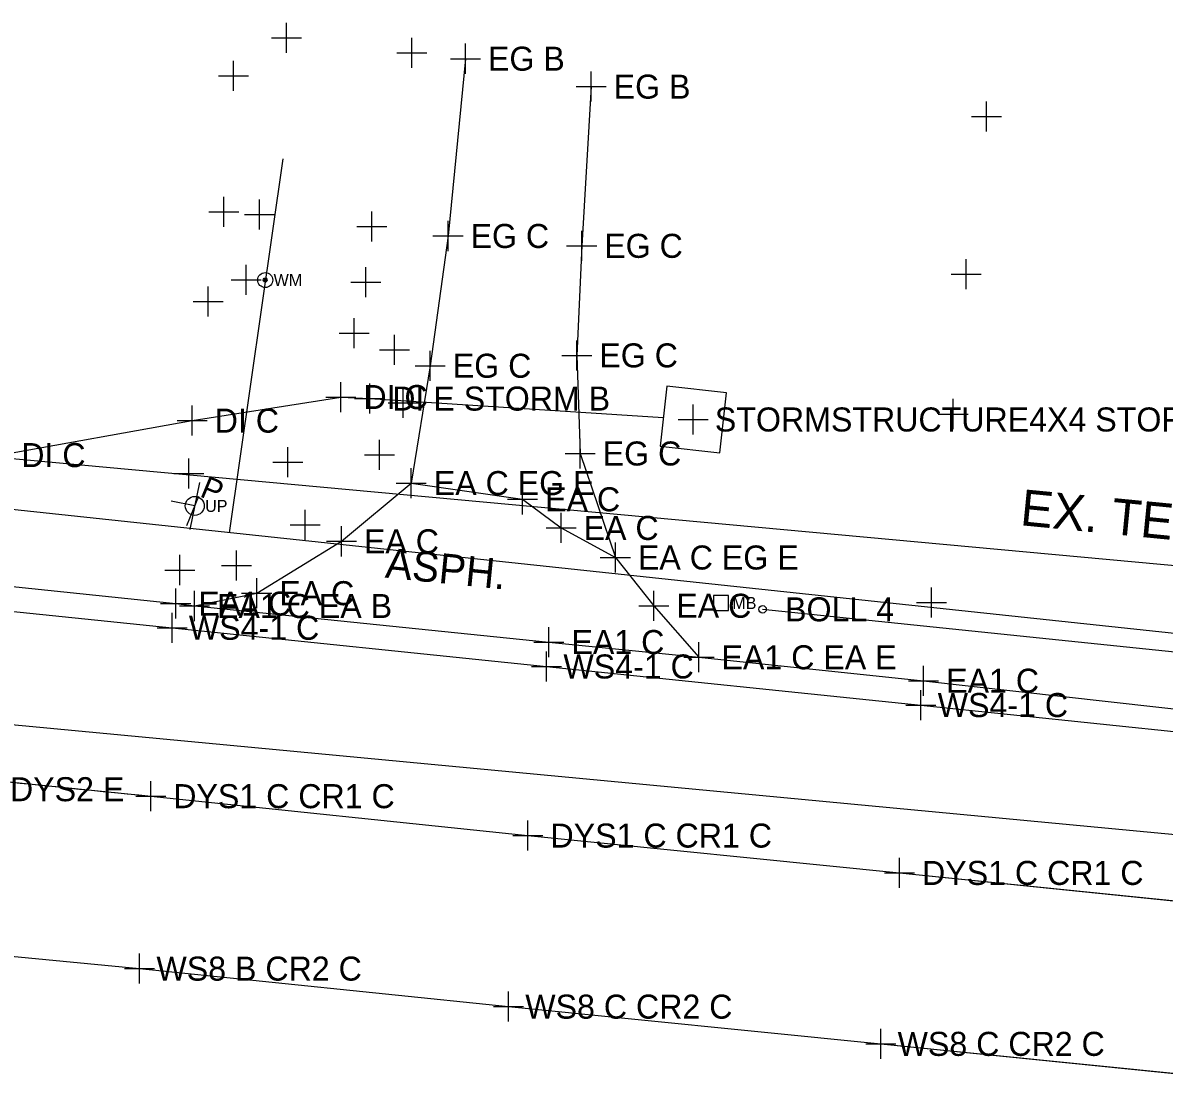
# Model space of a CAD drawing. Extents: x 1363693 to 1365209, y 422201 to 424153.
# Drawn here: x 1363888 to 1363964, y 423133.2 to 423203.8 of the extents above; entities that cross this region are included whole.
import ezdxf

# ---------------------------------------------------------------- set-up
doc = ezdxf.new("R2010")
doc.units = 0
for name, color, linetype in [('DR_X_Cells', 7, 'Continuous'), ('DR_X_Ditch', 7, 'Continuous'), ('DR_X_Storm_Sewer', 7, 'Continuous'), ('O-ALGN-BASELINE-WERK-CL-RW', 7, 'Continuous'), ('OWNERS', 7, 'Continuous'), ('PM_X_Channelizing_Line', 7, 'Continuous'), ('PM_X_CL_Double_Solid', 7, 'Continuous'), ('PM_X_Edge_Line', 7, 'Continuous'), ('PV_X_Driveway', 7, 'Continuous'), ('RD_X_Misc_Items', 7, 'Continuous'), ('RD_X_Text', 7, 'Continuous'), ('SN_X_Public', 7, 'Continuous'), ('SV_X_Original_Ground', 7, 'Continuous'), ('SV_X_Shot_Marker', 7, 'Continuous'), ('UT_X_Misc_Cells', 7, 'Continuous'), ('UT_X_Telecom_FO', 7, 'Continuous'), ('UT_X_Telecom_Text', 7, 'Continuous'), ('UT_X_Unknown_Cells', 7, 'Continuous'), ('UT_X_Water', 7, 'Continuous'), ('UT_X_Water_Text', 7, 'Continuous')]:
    doc.layers.add(name, color=color, linetype=linetype)

msp = doc.modelspace()

# ---------------------------------------------------------------- linework, layer by layer
at = {"layer": 'DR_X_Cells'}
msp.add_lwpolyline([(1363930.439, 423175.618), (1363934.414, 423175.175), (1363934.857, 423179.15), (1363930.882, 423179.593)], close=True, dxfattribs=at)
msp.add_lwpolyline([(1363930.439, 423175.618), (1363934.414, 423175.175), (1363934.857, 423179.15), (1363930.882, 423179.593)], close=True, dxfattribs=at)
at = {"layer": 'DR_X_Ditch'}
for p, q in [((1363899.298, 423177.309), (1363909.19, 423178.878)), ((1363899.298, 423177.309), (1363909.19, 423178.878)), ((1363909.19, 423178.878), (1363911.113, 423178.776)), ((1363909.19, 423178.878), (1363911.113, 423178.776)), ((1363886.422, 423175.014), (1363899.298, 423177.309)), ((1363886.422, 423175.014), (1363899.298, 423177.309))]:
    msp.add_line(p, q, dxfattribs=at)
at = {"layer": 'DR_X_Storm_Sewer'}
msp.add_line((1363911.113, 423178.776), (1363930.65, 423177.513), dxfattribs=at)
msp.add_line((1363911.113, 423178.776), (1363930.65, 423177.513), dxfattribs=at)
at = {"layer": 'O-ALGN-BASELINE-WERK-CL-RW'}
for points in [[(1363796.941, 423162.598), (1363822.036, 423159.943), (1363846.84, 423157.4), (1363871.296, 423154.865), (1363896.538, 423152.307), (1363921.646, 423149.685), (1363946.375, 423147.199), (1363971.317, 423144.667)], [(1363796.066, 423152.4), (1363820.538, 423149.019), (1363870.147, 423143.298), (1363895.8, 423140.828), (1363920.348, 423138.297), (1363945.13, 423135.819), (1363969.932, 423133.318)]]:
    msp.add_lwpolyline(points, dxfattribs=at)
at = {"layer": 'OWNERS'}
for points in [[(1363798.682, 423175.613), (1363823.663, 423174.201), (1363833.723, 423173.351), (1363848.588, 423171.533), (1363855.604, 423170.527), (1363873.275, 423167.734), (1363898.2, 423165.13), (1363899.452, 423164.968), (1363923.042, 423162.567), (1363933.03, 423161.553), (1363947.981, 423159.993), (1363972.757, 423157.214), (1363997.631, 423154.599), (1364022.422, 423152.18), (1364047.381, 423149.744), (1364072.232, 423147.292), (1364097.055, 423144.216), (1364103.808, 423143.454)], [(1363899.452, 423164.968), (1363903.591, 423165.821), (1363909.229, 423169.273), (1363913.878, 423173.149), (1363921.291, 423172.069), (1363923.85, 423170.164), (1363927.464, 423168.196), (1363930.02, 423164.983), (1363933.03, 423161.553)]]:
    msp.add_lwpolyline(points, dxfattribs=at)
at = {"layer": 'PM_X_Channelizing_Line'}
for p, q in [((1363873.089, 423166.093), (1363897.96, 423163.517)), ((1363897.96, 423163.517), (1363922.888, 423160.941)), ((1363922.888, 423160.941), (1363947.8, 423158.373)), ((1363947.8, 423158.373), (1363972.601, 423155.781)), ((1363896.538, 423152.307), (1363921.646, 423149.685)), ((1363921.646, 423149.685), (1363946.375, 423147.199)), ((1363946.375, 423147.199), (1363971.317, 423144.667)), ((1363895.8, 423140.828), (1363920.348, 423138.297)), ((1363895.8, 423140.828), (1363920.348, 423138.297)), ((1363920.348, 423138.297), (1363945.13, 423135.819)), ((1363920.348, 423138.297), (1363945.13, 423135.819)), ((1363945.13, 423135.819), (1363969.932, 423133.318)), ((1363945.13, 423135.819), (1363969.932, 423133.318))]:
    msp.add_line(p, q, dxfattribs=at)
msp.add_arc((1364982.521, 433994.461), 10896.406, 264.1467514, 264.2801594, dxfattribs=at)
at = {"layer": 'PM_X_CL_Double_Solid'}
for p, q in [((1363896.538, 423152.307), (1363921.646, 423149.685)), ((1363921.646, 423149.685), (1363946.375, 423147.199)), ((1363946.375, 423147.199), (1363971.317, 423144.667))]:
    msp.add_line(p, q, dxfattribs=at)
msp.add_arc((1364982.521, 433994.461), 10896.406, 264.1467514, 264.2801594, dxfattribs=at)
at = {"layer": 'PM_X_Edge_Line'}
for p, q in [((1363873.089, 423166.093), (1363897.96, 423163.517)), ((1363897.96, 423163.517), (1363922.888, 423160.941)), ((1363922.888, 423160.941), (1363947.8, 423158.373)), ((1363947.8, 423158.373), (1363972.601, 423155.781))]:
    msp.add_line(p, q, dxfattribs=at)
at = {"layer": 'PV_X_Driveway'}
for points in [[(1363917.485, 423201.403), (1363916.326, 423189.6), (1363915.143, 423180.962), (1363913.878, 423173.149)], [(1363925.853, 423199.542), (1363925.223, 423188.944), (1363924.898, 423181.65), (1363925.122, 423175.12), (1363927.464, 423168.196)]]:
    msp.add_lwpolyline(points, dxfattribs=at)
at = {"layer": 'RD_X_Misc_Items'}
for p, q in [((1363934.999, 423165.668), (1363933.999, 423165.668)), ((1363933.999, 423165.668), (1363933.999, 423164.668)), ((1363934.999, 423164.668), (1363934.999, 423165.668)), ((1363933.999, 423164.668), (1363934.999, 423164.668))]:
    msp.add_line(p, q, dxfattribs=at)
msp.add_lwpolyline([(1363937.261, 423164.746), (1363974.765, 423160.866), (1364012.563, 423155.911)], dxfattribs=at)
msp.add_lwpolyline([(1363937.261, 423164.746), (1363974.765, 423160.866), (1364012.563, 423155.911)], dxfattribs=at)
at = {"layer": 'SN_X_Public'}
for p, q in [((1363899.795, 423173.197), (1363899.149, 423170.063)), ((1363899.472, 423171.63), (1363897.905, 423171.953))]:
    msp.add_line(p, q, dxfattribs=at)
at = {"layer": 'SV_X_Original_Ground'}
for p, q in [((1363905.585, 423201.79), (1363905.585, 423203.79)), ((1363904.585, 423202.79), (1363906.585, 423202.79)), ((1363913.91, 423200.799), (1363913.91, 423202.799)), ((1363902.051, 423199.268), (1363902.051, 423201.268)), ((1363912.91, 423201.799), (1363914.91, 423201.799)), ((1363901.051, 423200.268), (1363903.051, 423200.268)), ((1363952.165, 423196.552), (1363952.165, 423198.552)), ((1363951.165, 423197.552), (1363953.165, 423197.552)), ((1363901.402, 423190.213), (1363901.402, 423192.213)), ((1363903.772, 423190.039), (1363903.772, 423192.039)), ((1363900.402, 423191.213), (1363902.402, 423191.213)), ((1363902.772, 423191.039), (1363904.772, 423191.039)), ((1363911.259, 423189.232), (1363911.259, 423191.232)), ((1363910.259, 423190.232), (1363912.259, 423190.232)), ((1363902.887, 423185.672), (1363902.887, 423187.672)), ((1363910.858, 423185.518), (1363910.858, 423187.518)), ((1363950.821, 423186.066), (1363950.821, 423188.066)), ((1363949.821, 423187.066), (1363951.821, 423187.066)), ((1363900.368, 423184.23), (1363900.368, 423186.23)), ((1363901.887, 423186.672), (1363903.887, 423186.672)), ((1363909.858, 423186.518), (1363911.858, 423186.518)), ((1363899.368, 423185.23), (1363901.368, 423185.23)), ((1363910.089, 423182.138), (1363910.089, 423184.138)), ((1363909.089, 423183.138), (1363911.089, 423183.138)), ((1363912.755, 423181.03), (1363912.755, 423183.03)), ((1363911.755, 423182.03), (1363913.755, 423182.03)), ((1363913.334, 423177.487), (1363913.334, 423179.487)), ((1363912.334, 423178.487), (1363914.334, 423178.487)), ((1363949.956, 423176.748), (1363949.956, 423178.748)), ((1363932.648, 423176.384), (1363932.648, 423178.384)), ((1363948.956, 423177.748), (1363950.956, 423177.748)), ((1363931.648, 423177.384), (1363933.648, 423177.384)), ((1363905.668, 423173.539), (1363905.668, 423175.539)), ((1363911.758, 423174.028), (1363911.758, 423176.028)), ((1363899.069, 423172.78), (1363899.069, 423174.78)), ((1363910.758, 423175.028), (1363912.758, 423175.028)), ((1363904.668, 423174.539), (1363906.668, 423174.539)), ((1363898.069, 423173.78), (1363900.069, 423173.78)), ((1363906.818, 423169.363), (1363906.818, 423171.363)), ((1363905.818, 423170.363), (1363907.818, 423170.363)), ((1363902.251, 423166.666), (1363902.251, 423168.666)), ((1363898.47, 423166.363), (1363898.47, 423168.363)), ((1363897.47, 423167.363), (1363899.47, 423167.363)), ((1363901.251, 423167.666), (1363903.251, 423167.666)), ((1363948.51, 423164.199), (1363948.51, 423166.199)), ((1363947.51, 423165.199), (1363949.51, 423165.199)), ((1363897.96, 423162.517), (1363897.96, 423164.517)), ((1363896.96, 423163.517), (1363898.96, 423163.517)), ((1363922.888, 423159.941), (1363922.888, 423161.941)), ((1363921.888, 423160.941), (1363923.888, 423160.941)), ((1363947.8, 423157.373), (1363947.8, 423159.373)), ((1363946.8, 423158.373), (1363948.8, 423158.373)), ((1363896.538, 423151.307), (1363896.538, 423153.307)), ((1363895.538, 423152.307), (1363897.538, 423152.307)), ((1363921.646, 423148.685), (1363921.646, 423150.685)), ((1363920.646, 423149.685), (1363922.646, 423149.685)), ((1363946.375, 423146.199), (1363946.375, 423148.199)), ((1363945.375, 423147.199), (1363947.375, 423147.199)), ((1363895.8, 423139.828), (1363895.8, 423141.828)), ((1363894.8, 423140.828), (1363896.8, 423140.828)), ((1363920.348, 423137.297), (1363920.348, 423139.297)), ((1363919.348, 423138.297), (1363921.348, 423138.297)), ((1363945.13, 423134.819), (1363945.13, 423136.819)), ((1363944.13, 423135.819), (1363946.13, 423135.819))]:
    msp.add_line(p, q, dxfattribs=at)
at = {"layer": 'SV_X_Shot_Marker'}
for p, q in [((1363917.485, 423200.403), (1363917.485, 423202.403)), ((1363916.485, 423201.403), (1363918.485, 423201.403)), ((1363925.853, 423198.542), (1363925.853, 423200.542)), ((1363924.853, 423199.542), (1363926.853, 423199.542)), ((1363916.326, 423188.6), (1363916.326, 423190.6)), ((1363925.223, 423187.944), (1363925.223, 423189.944)), ((1363915.326, 423189.6), (1363917.326, 423189.6)), ((1363924.223, 423188.944), (1363926.223, 423188.944)), ((1363924.898, 423180.65), (1363924.898, 423182.65)), ((1363915.143, 423179.962), (1363915.143, 423181.962)), ((1363923.898, 423181.65), (1363925.898, 423181.65)), ((1363914.143, 423180.962), (1363916.143, 423180.962)), ((1363909.19, 423177.878), (1363909.19, 423179.878)), ((1363911.113, 423177.776), (1363911.113, 423179.776)), ((1363908.19, 423178.878), (1363910.19, 423178.878)), ((1363910.113, 423178.776), (1363912.113, 423178.776)), ((1363899.298, 423176.309), (1363899.298, 423178.309)), ((1363898.298, 423177.309), (1363900.298, 423177.309)), ((1363925.122, 423174.12), (1363925.122, 423176.12)), ((1363924.122, 423175.12), (1363926.122, 423175.12)), ((1363913.878, 423172.149), (1363913.878, 423174.149)), ((1363912.878, 423173.149), (1363914.878, 423173.149)), ((1363921.291, 423171.069), (1363921.291, 423173.069)), ((1363920.291, 423172.069), (1363922.291, 423172.069)), ((1363923.85, 423169.164), (1363923.85, 423171.164)), ((1363909.229, 423168.273), (1363909.229, 423170.273)), ((1363922.85, 423170.164), (1363924.85, 423170.164)), ((1363908.229, 423169.273), (1363910.229, 423169.273)), ((1363927.464, 423167.196), (1363927.464, 423169.196)), ((1363926.464, 423168.196), (1363928.464, 423168.196)), ((1363903.591, 423164.821), (1363903.591, 423166.821)), ((1363898.2, 423164.13), (1363898.2, 423166.13)), ((1363899.452, 423163.968), (1363899.452, 423165.968)), ((1363902.591, 423165.821), (1363904.591, 423165.821)), ((1363930.02, 423163.983), (1363930.02, 423165.983)), ((1363897.2, 423165.13), (1363899.2, 423165.13)), ((1363898.452, 423164.968), (1363900.452, 423164.968)), ((1363929.02, 423164.983), (1363931.02, 423164.983)), ((1363923.042, 423161.567), (1363923.042, 423163.567)), ((1363922.042, 423162.567), (1363924.042, 423162.567)), ((1363933.03, 423160.553), (1363933.03, 423162.553)), ((1363932.03, 423161.553), (1363934.03, 423161.553)), ((1363947.981, 423158.993), (1363947.981, 423160.993)), ((1363946.981, 423159.993), (1363948.981, 423159.993))]:
    msp.add_line(p, q, dxfattribs=at)
msp.add_circle((1363937.261, 423164.746), 0.25, dxfattribs=at)
at = {"layer": 'UT_X_Telecom_FO'}
msp.add_line((1363800.763, 423182.733), (1364009.31, 423163.557), dxfattribs=at)
at = {"layer": 'UT_X_Unknown_Cells'}
msp.add_line((1363898.938, 423170.336), (1363899.741, 423172.281), dxfattribs=at)
msp.add_circle((1363899.472, 423171.63), 0.63, dxfattribs=at)
at = {"layer": 'UT_X_Water'}
msp.add_line((1363901.788, 423169.834), (1363905.348, 423194.733), dxfattribs=at)
for points in [[(1363904.092, 423186.781), (1363904.159, 423186.666), (1363904.159, 423186.666), (1363904.044, 423186.733)], [(1363904.159, 423186.799), (1363904.159, 423186.666), (1363904.159, 423186.666), (1363904.092, 423186.781)], [(1363904.226, 423186.781), (1363904.159, 423186.666), (1363904.159, 423186.666), (1363904.159, 423186.799)], [(1363904.274, 423186.733), (1363904.159, 423186.666), (1363904.159, 423186.666), (1363904.226, 423186.781)], [(1363904.044, 423186.733), (1363904.159, 423186.666), (1363904.159, 423186.666), (1363904.026, 423186.666)], [(1363904.026, 423186.666), (1363904.159, 423186.666), (1363904.159, 423186.666), (1363904.044, 423186.599)], [(1363904.044, 423186.599), (1363904.159, 423186.666), (1363904.159, 423186.666), (1363904.092, 423186.551)], [(1363904.092, 423186.551), (1363904.159, 423186.666), (1363904.159, 423186.666), (1363904.159, 423186.533)], [(1363904.292, 423186.666), (1363904.159, 423186.666), (1363904.159, 423186.666), (1363904.274, 423186.733)], [(1363904.159, 423186.533), (1363904.159, 423186.666), (1363904.159, 423186.666), (1363904.226, 423186.551)], [(1363904.226, 423186.551), (1363904.159, 423186.666), (1363904.159, 423186.666), (1363904.274, 423186.599)], [(1363904.274, 423186.599), (1363904.159, 423186.666), (1363904.159, 423186.666), (1363904.292, 423186.666)]]:
    msp.add_lwpolyline(points, close=True, dxfattribs=at)
for points in [[(1363800.135, 423180.715), (1364166.64, 423141.621), (1364199.33, 423140.767)], [(1363797.978, 423165.496), (1364047.142, 423141.995), (1364047.135, 423142.005), (1364251.213, 423122.543), (1364692.365, 423076.33)]]:
    msp.add_lwpolyline(points, dxfattribs=at)
msp.add_circle((1363904.159, 423186.666), 0.5, dxfattribs=at)

# ---------------------------------------------------------------- texts
at = {"layer": 'RD_X_Text'}
msp.add_text('ASPH.', height=2, rotation=354.30306, dxfattribs=at).set_placement((1363912.094, 423166.861))
msp.add_text('MB', height=0.8, dxfattribs=at).set_placement((1363935.249, 423164.768))
at = {"layer": 'SV_X_Original_Ground'}
for s, p in [('STORMSTRUCTURE4X4 STORM E', (1363934.087, 423176.584)), ('WS4-1 C', (1363899.079, 423162.717)), ('WS4-1 C', (1363924.007, 423160.141)), ('WS4-1 C', (1363948.919, 423157.573)), ('DYS2 E', (1363887.171, 423151.972)), ('DYS1 C CR1 C', (1363898.038, 423151.507)), ('DYS1 C CR1 C', (1363923.146, 423148.885)), ('DYS1 C CR1 C', (1363947.875, 423146.399)), ('WS8 B CR2 C', (1363896.919, 423140.028)), ('WS8 C CR2 C', (1363921.467, 423137.497)), ('WS8 C CR2 C', (1363946.249, 423135.019))]:
    msp.add_text(s, height=1.6, dxfattribs=at).set_placement(p)
at = {"layer": 'SV_X_Shot_Marker'}
for s, p in [('EG B', (1363918.985, 423200.603)), ('EG B', (1363927.353, 423198.742)), ('EG C', (1363917.826, 423188.8)), ('EG C', (1363926.723, 423188.144)), ('EG C', (1363926.398, 423180.85)), ('EG C', (1363916.643, 423180.162)), ('DI C', (1363910.69, 423178.078)), ('DI E STORM B', (1363912.613, 423177.976)), ('DI C', (1363900.798, 423176.509)), ('DI C', (1363887.922, 423174.214)), ('EG C', (1363926.622, 423174.32)), ('EA C EG E', (1363915.378, 423172.349)), ('EA C', (1363922.791, 423171.269)), ('EA C', (1363925.35, 423169.364)), ('EA C', (1363910.729, 423168.473)), ('EA C EG E', (1363928.964, 423167.396)), ('EA C', (1363905.091, 423165.021)), ('EA1 C', (1363899.7, 423164.33)), ('EA1 C EA B', (1363900.952, 423164.168)), ('EA C', (1363931.52, 423164.183)), ('BOLL 4', (1363938.761, 423163.946)), ('EA1 C', (1363924.542, 423161.767)), ('EA1 C EA E', (1363934.53, 423160.753)), ('EA1 C', (1363949.481, 423159.193))]:
    msp.add_text(s, height=1.6, dxfattribs=at).set_placement(p)
at = {"layer": 'UT_X_Misc_Cells'}
msp.add_text('UP', height=0.8, dxfattribs=at).set_placement((1363900.161, 423171.23))
at = {"layer": 'UT_X_Telecom_Text'}
msp.add_text('EX. TELECOMM', height=2.4, rotation=354.4298, dxfattribs=at).set_placement((1363954.36, 423170.354))
at = {"layer": 'UT_X_Unknown_Cells'}
msp.add_text('P', height=1.503, rotation=337.58271, dxfattribs=at).set_placement((1363899.741, 423172.281))
at = {"layer": 'UT_X_Water_Text'}
msp.add_text('WM', height=0.8, dxfattribs=at).set_placement((1363904.719, 423186.266))

doc.saveas('drawing.dxf')
